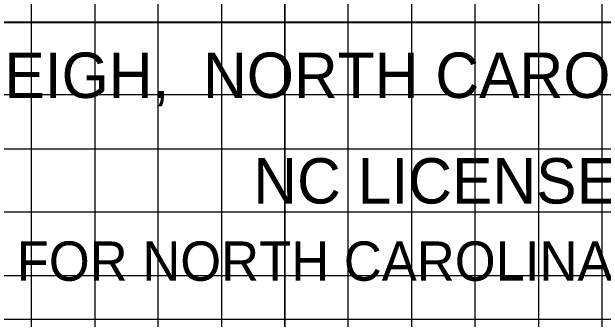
# Model space of a CAD drawing. Extents: x 2195312 to 2197193, y 76953 to 78053.
# Drawn here: x 2196657.19 to 2196703.84, y 77979.23 to 78003.45 of the extents above; entities that cross this region are included whole.
import ezdxf

# ---------------------------------------------------------------- set-up
doc = ezdxf.new("R2010")
doc.units = 0
for name, color, linetype in [('Exist Structure Minor Culvert Topo Terminator', 7, 'Continuous'), ('Old_Level_3', 7, 'Continuous'), ('Sheet Cutting Line CELL', 7, 'Continuous'), ('Sheet Data Field CELL', 7, 'Continuous'), ('Sheet Plot Border Outside CELL', 7, 'Continuous'), ('Sheet Sticker Preliminary CELL', 7, 'Continuous')]:
    doc.layers.add(name, color=color, linetype=linetype)

msp = doc.modelspace()

# ---------------------------------------------------------------- linework, layer by layer
at = {"layer": 'Old_Level_3'}
msp.add_lwpolyline([(2196644.279, 77979.233), (2196778.679, 77979.233), (2196778.679, 78027.661), (2196644.279, 78027.661)], close=True, dxfattribs=at)
at = {"layer": 'Sheet Cutting Line CELL'}
for points in [[(2196678.729, 77002.661), (2196678.729, 78027.661), (2196728.729, 78027.661), (2196728.729, 77002.661)], [(2196778.679, 77952.661), (2195478.829, 77952.661), (2195478.829, 78002.611), (2196778.679, 78002.611)]]:
    msp.add_lwpolyline(points, dxfattribs=at)
at = {"layer": 'Sheet Data Field CELL'}
for points in [[(2196658.729, 77002.661), (2196658.729, 78027.661), (2196663.729, 78027.661), (2196663.729, 77002.661)], [(2196668.729, 77002.661), (2196668.729, 78027.661), (2196673.729, 78027.661), (2196673.729, 77002.661)], [(2196683.729, 77002.661), (2196683.729, 78027.661), (2196688.729, 78027.661), (2196688.729, 77002.661)], [(2196693.729, 77002.661), (2196693.729, 78027.661), (2196698.729, 78027.661), (2196698.729, 77002.661)], [(2196778.679, 77996.911), (2195529.729, 77996.911), (2195529.729, 77992.661), (2196778.679, 77992.661)], [(2196778.679, 77987.661), (2195528.729, 77987.661), (2195528.729, 77982.661), (2196778.679, 77982.661)]]:
    msp.add_lwpolyline(points, dxfattribs=at)
at = {"layer": 'Sheet Plot Border Outside CELL'}
msp.add_lwpolyline([(2196653.729, 77002.661), (2196653.729, 78027.661), (2196703.729, 78027.661), (2196703.729, 77002.661)], dxfattribs=at)
at = {"layer": 'Sheet Sticker Preliminary CELL'}
for p, q in [((2196678.729, 78027.661), (2196678.729, 77002.661)), ((2195478.729, 78002.661), (2196778.679, 78002.661))]:
    msp.add_line(p, q, dxfattribs=at)

# ---------------------------------------------------------------- texts
at = {"layer": 'Exist Structure Minor Culvert Topo Terminator'}
for s, height, rotation, p in [('RALEIGH,  NORTH CAROLINA, (919) 854-1345', 3.57538, 360, (2196647.297, 77996.664)), ('NC LICENSE NO. F-0246', 3.57538, 360, (2196676.236, 77988.343)), ('FOR NORTH CAROLINA DEPT. OF TRANSPORTATION', 3.10128, 359.9999, (2196657.573, 77982.256))]:
    msp.add_text(s, height=height, rotation=rotation, dxfattribs=at).set_placement(p)

doc.saveas('drawing.dxf')
